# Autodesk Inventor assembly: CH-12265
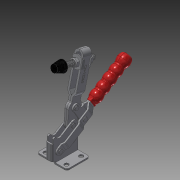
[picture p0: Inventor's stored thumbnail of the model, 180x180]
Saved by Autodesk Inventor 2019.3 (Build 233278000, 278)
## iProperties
Company: Î¢ÈíÖÐ¹ú
Created: 2012-09
Part Number: CH-12265
Material: Ogólny
Description: STEP AP203
Document SubType Name: Assembly
Designer: CADENGINEERING4
Stock Number: DOCISK PIONOWY
Sending System: SolidWorks 2010
Preprocessor: SwSTEP 2.0
Title: CH-12265.STEP
Author: Î¢ÈíÓÃ»§
Revision Number: ÈÎºÎ
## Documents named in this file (13)
- D:\Vault_2016\Projekty\Clamptek\STRONA\Vertical toggle clamp\CH-12265\CH-12265_OTWARTY.iam
- D:\Vault_2016\Projekty\Clamptek\STRONA\Vertical toggle clamp\CH-12265\CH-FC-38312 Nut.ipt
- D:\Vault_2016\Projekty\Clamptek\STRONA\Vertical toggle clamp\CH-12265\CH-12265-03 STRAIGHT HANDLE.ipt
- D:\Vault_2016\Projekty\Clamptek\STRONA\Vertical toggle clamp\CH-12265\CH-12265-05.ipt
- D:\Vault_2016\Projekty\Clamptek\STRONA\Vertical toggle clamp\CH-12265\CH-12265-08.ipt
- D:\Vault_2016\Projekty\Clamptek\STRONA\Vertical toggle clamp\CH-12265\CH-FW-380.ipt
- D:\Vault_2016\Projekty\Clamptek\STRONA\Vertical toggle clamp\CH-12265\CH-12265-07.ipt
- D:\Vault_2016\Projekty\Clamptek\STRONA\Vertical toggle clamp\CH-12265\CH-12265-01 FLANGED BASE.ipt
- D:\Vault_2016\Projekty\Clamptek\STRONA\Vertical toggle clamp\CH-12265\CH-12265-06.ipt
- D:\Vault_2016\Projekty\Clamptek\STRONA\Vertical toggle clamp\CH-12265\CH-12265-02 U-BAR.ipt
- D:\Vault_2016\Projekty\Clamptek\STRONA\Vertical toggle clamp\CH-12265\CH-12265-04 CONNECTING-PLATE.ipt
- D:\Vault_2016\Projekty\Clamptek\STRONA\Vertical toggle clamp\CH-12265\CH-FC-38312 SPINDLE SUPPLIED.ipt
- D:\Vault_2016\Projekty\Clamptek\STRONA\Vertical toggle clamp\CH-12265\CH-12265-09.ipt
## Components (18 placed, 18 different names)
1. CH-FC-38312 Nut_1 — Zestawiające:30, Zestawiające:31
2. CH-12265-03 STRAIGHT HANDLE_2 — Zestawiające:8, Zestawiające:9, Zestawiające:10, Zestawiające:11, Zestawiające:13, Zestawiające:14, Zestawiające:20, Zestawiające:21, Zestawiające:22, Zestawiające:34
3. CH-12265-05_3 — Zestawiające:4
4. CH-12265-08_4 — Zestawiające:17, Zestawiające:18, Zestawiające:19
5. CH-FW-380_5 — Zestawiające:24, Zestawiające:26, Kątowe:2, Zestawiające:29, Zestawiające:32, Równoległe:4
6. CH-12265-05_6 — Równoległe:1, Zestawiające:1, Zestawiające:2
7. CH-12265-08_7 — Zestawiające:15, Zestawiające:16
8. CH-12265-07_8 — Zestawiające:20, Zestawiające:21, Zestawiające:22
9. CH-12265-01 FLANGED BASE_9 — Zestawiające:4, Zestawiające:5, Równoległe:3, Zestawiające:7, Zestawiające:8, Zestawiające:17, Zestawiające:18, Zestawiające:34
10. CH-12265-06_10 — Równoległe:3, Zestawiające:7, Zestawiające:9
11. CH-FC-38312 Nut_11 — Zestawiające:29, Zestawiające:32, Zestawiające:33
12. CH-12265-02 U-BAR_12 — Równoległe:1, Zestawiające:1, Zestawiające:3, Zestawiające:5, Zestawiające:19, Zestawiające:24, Zestawiające:25, Zestawiające:27, Zestawiające:28, Kątowe:1, Kątowe:2
13. CH-12265-04 CONNECTING-PLATE_13 — Zestawiające:2, Zestawiające:3, Równoległe:2, Zestawiające:6, Zestawiające:15, Zestawiające:16
14. CH-FC-38312 SPINDLE SUPPLIED_14 — Zestawiające:33, Równoległe:4
15. CH-12265-06_15 — Równoległe:2, Zestawiające:6, Zestawiające:10, Zestawiające:12
16. CH-12265-09_16 — Zestawiające:13, Zestawiające:14
17. CH-FW-380_17 — Zestawiające:25, Zestawiające:26, Zestawiające:27, Zestawiające:28, Kątowe:1, Zestawiające:30, Zestawiające:31
18. CH-12265-09_18 — Zestawiające:11, Zestawiające:12
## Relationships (39: Mate 33, Flush 4, Angle 2)
- Równoległe:1 [Flush]: CH-12265-05_6 ↔ CH-12265-02 U-BAR_12
- Zestawiające:1 [Mate]: CH-12265-05_6 ↔ CH-12265-02 U-BAR_12
- Zestawiające:2 [Mate]: CH-12265-05_6 ↔ CH-12265-04 CONNECTING-PLATE_13
- Zestawiające:3 [Mate]: CH-12265-02 U-BAR_12 ↔ CH-12265-04 CONNECTING-PLATE_13
- Zestawiające:4 [Mate]: CH-12265-05_3 ↔ CH-12265-01 FLANGED BASE_9
- Zestawiające:5 [Mate]: CH-12265-01 FLANGED BASE_9 ↔ CH-12265-02 U-BAR_12
- Równoległe:2 [Flush]: CH-12265-04 CONNECTING-PLATE_13 ↔ CH-12265-06_15
- Zestawiające:6 [Mate]: CH-12265-04 CONNECTING-PLATE_13 ↔ CH-12265-06_15
- Równoległe:3 [Flush]: CH-12265-01 FLANGED BASE_9 ↔ CH-12265-06_10
- Zestawiające:7 [Mate]: CH-12265-01 FLANGED BASE_9 ↔ CH-12265-06_10
- Zestawiające:8 [Mate]: CH-12265-03 STRAIGHT HANDLE_2 ↔ CH-12265-01 FLANGED BASE_9
- Zestawiające:9 [Mate]: CH-12265-03 STRAIGHT HANDLE_2 ↔ CH-12265-06_10
- Zestawiające:10 [Mate]: CH-12265-03 STRAIGHT HANDLE_2 ↔ CH-12265-06_15
- Zestawiające:11 [Mate]: CH-12265-03 STRAIGHT HANDLE_2 ↔ CH-12265-09_18
- Zestawiające:12 [Mate]: CH-12265-06_15 ↔ CH-12265-09_18
- Zestawiające:13 [Mate]: CH-12265-03 STRAIGHT HANDLE_2 ↔ CH-12265-09_16
- Zestawiające:14 [Mate]: CH-12265-03 STRAIGHT HANDLE_2 ↔ CH-12265-09_16
- Zestawiające:15 [Mate]: CH-12265-08_7 ↔ CH-12265-04 CONNECTING-PLATE_13
- Zestawiające:16 [Mate]: CH-12265-08_7 ↔ CH-12265-04 CONNECTING-PLATE_13
- Zestawiające:17 [Mate]: CH-12265-08_4 ↔ CH-12265-01 FLANGED BASE_9
- Zestawiające:18 [Mate]: CH-12265-08_4 ↔ CH-12265-01 FLANGED BASE_9
- Zestawiające:19 [Mate]: CH-12265-08_4 ↔ CH-12265-02 U-BAR_12
- Zestawiające:20 [Mate]: CH-12265-03 STRAIGHT HANDLE_2 ↔ CH-12265-07_8
- Zestawiające:21 [Mate]: CH-12265-03 STRAIGHT HANDLE_2 ↔ CH-12265-07_8
- Zestawiające:22 [Mate]: CH-12265-03 STRAIGHT HANDLE_2 ↔ CH-12265-07_8
- Zestawiające:24 [Mate]: CH-FW-380_5 ↔ CH-12265-02 U-BAR_12
- Zestawiające:25 [Mate]: CH-12265-02 U-BAR_12 ↔ CH-FW-380_17
- Zestawiające:26 [Mate]: CH-FW-380_5 ↔ CH-FW-380_17
- Zestawiające:27 [Mate]: CH-12265-02 U-BAR_12 ↔ CH-FW-380_17
- Zestawiające:28 [Mate]: CH-12265-02 U-BAR_12 ↔ CH-FW-380_17
- Kątowe:1 [Angle]: CH-12265-02 U-BAR_12 ↔ CH-FW-380_17
- Kątowe:2 [Angle]: CH-FW-380_5 ↔ CH-12265-02 U-BAR_12
- Zestawiające:29 [Mate]: CH-FW-380_5 ↔ CH-FC-38312 Nut_11
- Zestawiające:30 [Mate]: CH-FC-38312 Nut_1 ↔ CH-FW-380_17
- Zestawiające:31 [Mate]: CH-FC-38312 Nut_1 ↔ CH-FW-380_17
- Zestawiające:32 [Mate]: CH-FW-380_5 ↔ CH-FC-38312 Nut_11
- Zestawiające:33 [Mate]: CH-FC-38312 Nut_11 ↔ CH-FC-38312 SPINDLE SUPPLIED_14
- Równoległe:4 [Flush]: CH-FW-380_5 ↔ CH-FC-38312 SPINDLE SUPPLIED_14
- Zestawiające:34 [Mate]: CH-12265-03 STRAIGHT HANDLE_2 ↔ CH-12265-01 FLANGED BASE_9
